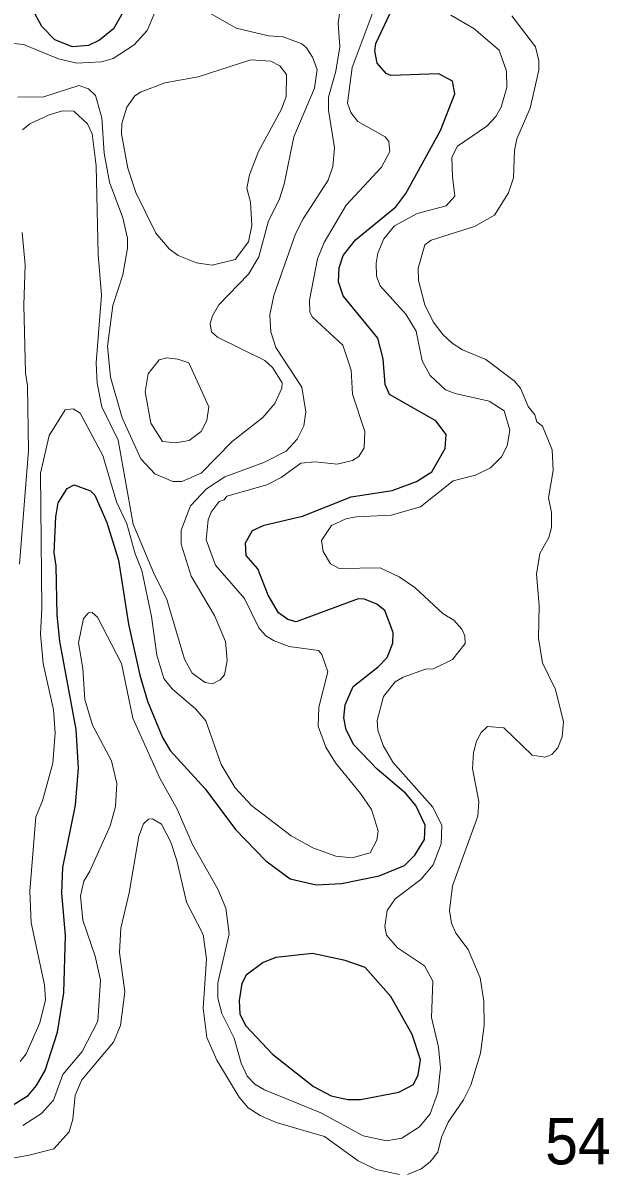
# Model space of a CAD drawing. Extents: x 673.6 to 698.9, y 7012 to 7040.1.
# Drawn here: x 681.449 to 682.459, y 7032.142 to 7034.12 of the extents above; entities that cross this region are included whole.
import ezdxf

# ---------------------------------------------------------------- set-up
doc = ezdxf.new("R2010")
doc.units = 0
doc.header["$LTSCALE"] = 0.032
doc.layers.add('1', color=7, linetype='Continuous', lineweight=25)
doc.layers.add('2', color=7, linetype='Continuous', lineweight=13)
doc.layers.add('21', color=7, linetype='Continuous')

msp = doc.modelspace()

# ---------------------------------------------------------------- linework, layer by layer
at = {"layer": '1'}
for points in [[(681.6055, 7034.1099), (681.5815, 7034.0904), (681.5621, 7034.0813), (681.5348, 7034.0789), (681.5041, 7034.0912), (681.4821, 7034.1139), (681.4666, 7034.1429), (681.4563, 7034.1779), (681.4556, 7034.1951), (681.4592, 7034.2083), (681.4778, 7034.2292), (681.4971, 7034.2413), (681.5311, 7034.2489), (681.5677, 7034.2464), (681.6015, 7034.231), (681.6232, 7034.214), (681.6297, 7034.1857), (681.6297, 7034.1606), (681.6192, 7034.1342)], [(682.0044, 7032.5048), (681.9485, 7032.5167), (681.8849, 7032.5102), (681.8631, 7032.5011), (681.8341, 7032.4793), (681.8267, 7032.4654), (681.8221, 7032.4357), (681.8228, 7032.4124), (681.8333, 7032.3919), (681.8796, 7032.3434), (681.95, 7032.2878), (681.9805, 7032.2715), (682.009, 7032.2653), (682.0308, 7032.2653), (682.0969, 7032.2777), (682.122, 7032.2909), (682.1301, 7032.3075), (682.1342, 7032.3334), (682.1197, 7032.3774), (682.0831, 7032.4428), (682.039, 7032.4928)]]:
    msp.add_lwpolyline(points, close=True, dxfattribs=at)
for points in [[(681.5066, 7033.1847), (681.5033, 7033.2074), (681.5062, 7033.2691), (681.5102, 7033.2932), (681.5255, 7033.318), (681.5376, 7033.3244), (681.5656, 7033.3138), (681.573, 7033.3064), (681.594, 7033.2596), (681.6142, 7033.1943), (681.6315, 7033.0842), (681.6505, 7032.9965), (681.6641, 7032.9514), (681.6898, 7032.8889), (681.7032, 7032.8667), (681.7631, 7032.8007), (681.8154, 7032.7303), (681.868, 7032.6763), (681.91, 7032.6455), (681.9548, 7032.6351), (681.9983, 7032.6376), (682.0628, 7032.6504), (682.1069, 7032.6686), (682.1244, 7032.6861), (682.1409, 7032.7132), (682.1425, 7032.7382), (682.1263, 7032.772), (682.1085, 7032.7931), (682.0595, 7032.8347), (682.0195, 7032.8763), (682.0062, 7032.9022), (682.0021, 7032.9227), (682.0046, 7032.9452), (682.0185, 7032.9769), (682.0614, 7033.0108), (682.0768, 7033.0266), (682.0867, 7033.0516), (682.0873, 7033.0701), (682.0728, 7033.1079), (682.059, 7033.1188), (682.0377, 7033.1271), (682.027, 7033.128), (681.9203, 7033.088), (681.9059, 7033.092), (681.8896, 7033.1035), (681.8717, 7033.1341), (681.8542, 7033.1795), (681.8338, 7033.2027), (681.8328, 7033.2242), (681.8451, 7033.2455), (681.8649, 7033.2546), (681.9309, 7033.2704), (682.0148, 7033.3039), (682.0854, 7033.3147), (682.1274, 7033.3301), (682.1537, 7033.3466), (682.1767, 7033.3872), (682.1784, 7033.4111), (682.1605, 7033.4346), (682.081, 7033.4799), (682.0736, 7033.4971), (682.0702, 7033.5414), (682.0606, 7033.5768), (682.001, 7033.6499), (681.993, 7033.6742), (681.9939, 7033.6983), (682.0009, 7033.7197), (682.0221, 7033.7463), (682.0919, 7033.8032), (682.109, 7033.8265), (682.169, 7033.9346), (682.1933, 7033.998), (682.1892, 7034.0196), (682.1659, 7034.0326), (682.0829, 7034.0295), (682.0751, 7034.0329), (682.0598, 7034.0506), (682.0555, 7034.072), (682.0572, 7034.0847), (682.0915, 7034.1577)], [(681.5401, 7032.7723), (681.545, 7032.8363), (681.541, 7032.9025), (681.513, 7033.0549), (681.5081, 7033.0997), (681.5066, 7033.1847)], [(681.4299, 7032.2541), (681.4585, 7032.2724), (681.4726, 7032.2895), (681.4876, 7032.3154), (681.509, 7032.3815), (681.5197, 7032.4489), (681.523, 7032.5477), (681.5164, 7032.6207), (681.518, 7032.665), (681.5401, 7032.7723)]]:
    msp.add_lwpolyline(points, dxfattribs=at)
at = {"layer": '2'}
for points in [[(681.997, 7034.1512), (681.9922, 7034.1199), (681.9954, 7034.0788), (681.9883, 7034.0373), (681.9758, 7033.9921), (681.9758, 7033.9697), (681.9863, 7033.905), (681.9834, 7033.873), (681.9751, 7033.8492), (681.932, 7033.7827), (681.9192, 7033.7567), (681.8815, 7033.6506), (681.8745, 7033.6174), (681.8762, 7033.5878), (681.8853, 7033.5611), (681.93, 7033.4926), (681.937, 7033.4502), (681.9335, 7033.4257), (681.9219, 7033.4028), (681.9027, 7033.3824), (681.8643, 7033.3628), (681.7971, 7033.3383), (681.7659, 7033.3177), (681.7381, 7033.288), (681.7218, 7033.246), (681.7219, 7033.2223), (681.739, 7033.1667), (681.7793, 7033.0993), (681.7983, 7033.0546), (681.8014, 7033.0214), (681.7968, 7032.9967), (681.7891, 7032.9882), (681.7758, 7032.9812), (681.7633, 7032.984), (681.7411, 7032.9996), (681.7276, 7033.0238), (681.6974, 7033.1267), (681.6741, 7033.1734), (681.6395, 7033.2563), (681.6134, 7033.4014), (681.5852, 7033.4588), (681.5773, 7033.4996), (681.5756, 7033.5345), (681.5846, 7033.6509), (681.5788, 7033.721), (681.5755, 7033.8738), (681.5689, 7033.9293), (681.5606, 7033.9465), (681.537, 7033.968), (681.5173, 7033.9686), (681.4947, 7033.962), (681.4615, 7033.9461), (681.4486, 7033.9362)], [(681.6765, 7034.138), (681.6636, 7034.1071), (681.641, 7034.0822), (681.6049, 7034.0586), (681.585, 7034.0534), (681.5423, 7034.051), (681.5106, 7034.0581), (681.4503, 7034.083), (681.4165, 7034.0862)], [(681.4407, 7033.9925), (681.4854, 7033.9926), (681.5459, 7034.0122), (681.5622, 7034.0067), (681.5745, 7033.9949), (681.5854, 7033.9569), (681.5895, 7033.8957), (681.5985, 7033.8459), (681.6216, 7033.7844), (681.6297, 7033.7492), (681.6297, 7033.7322), (681.6215, 7033.6861), (681.6042, 7033.6335), (681.5953, 7033.5633), (681.6002, 7033.5099), (681.6205, 7033.4397), (681.6526, 7033.3692), (681.6766, 7033.3434), (681.7074, 7033.3302), (681.7231, 7033.3302), (681.7565, 7033.3444), (681.8101, 7033.3988), (681.8628, 7033.4401), (681.8832, 7033.4644), (681.8956, 7033.4911), (681.896, 7033.5), (681.8795, 7033.5266), (681.8663, 7033.5388), (681.7845, 7033.5786), (681.7743, 7033.5881), (681.772, 7033.602), (681.776, 7033.6154), (681.7871, 7033.6345), (681.8381, 7033.6874), (681.8556, 7033.717), (681.8727, 7033.7791), (681.8909, 7033.8156), (681.8997, 7033.8423), (681.9163, 7033.9238), (681.9518, 7034.0079), (681.956, 7034.0398), (681.9483, 7034.0614), (681.9379, 7034.0772), (681.9297, 7034.0839), (681.8976, 7034.0961), (681.8723, 7034.0979), (681.8168, 7034.1111), (681.7738, 7034.1359)], [(681.5007, 7032.8446), (681.5048, 7032.8972), (681.5023, 7032.9366), (681.4842, 7033.0163), (681.4794, 7033.0673), (681.4819, 7033.1119), (681.4794, 7033.3446), (681.4948, 7033.4092), (681.5223, 7033.4534), (681.536, 7033.455), (681.5478, 7033.4477), (681.5873, 7033.3747), (681.6105, 7033.2952), (681.6281, 7033.2571), (681.6427, 7033.2053), (681.6544, 7033.1766), (681.6709, 7033.0974), (681.6798, 7033.0307), (681.6923, 7032.9909), (681.7062, 7032.9726), (681.7475, 7032.938), (681.7645, 7032.9177), (681.791, 7032.8426), (681.815, 7032.8025), (681.8429, 7032.7721), (681.9115, 7032.7193), (681.949, 7032.6989), (681.9884, 7032.6847), (682.0164, 7032.6819), (682.0478, 7032.6901), (682.0592, 7032.7123), (682.0612, 7032.7284), (682.0499, 7032.765), (682.031, 7032.7927), (681.9876, 7032.8453), (681.971, 7032.8722), (681.9581, 7032.9083), (681.9592, 7032.941), (681.9748, 7033.0023), (681.9642, 7033.0319), (681.9586, 7033.039), (681.9083, 7033.0457), (681.882, 7033.0554), (681.8678, 7033.0641), (681.8559, 7033.0779), (681.8308, 7033.1286), (681.7812, 7033.1861), (681.7653, 7033.2293), (681.7684, 7033.264), (681.7738, 7033.2772), (681.7874, 7033.2955), (681.7959, 7033.2985), (681.8009, 7033.3047), (681.8694, 7033.3244), (681.894, 7033.3367), (681.9284, 7033.3614), (681.9527, 7033.3639), (681.9909, 7033.3599), (682.0169, 7033.3661), (682.0278, 7033.3732), (682.0373, 7033.388), (682.0382, 7033.4162), (682.0172, 7033.4803), (682.0151, 7033.5217), (682.0003, 7033.5652), (681.9485, 7033.6134), (681.9437, 7033.622), (681.9432, 7033.6424), (681.9568, 7033.7137), (681.9681, 7033.7416), (682.0064, 7033.8063), (682.0669, 7033.8718), (682.0816, 7033.8984), (682.0795, 7033.916), (682.0732, 7033.9239), (682.0264, 7033.9503), (682.0142, 7033.9658), (682.0085, 7033.9822), (682.0165, 7034.0436), (682.0529, 7034.1397)], [(682.1864, 7034.1338), (682.2261, 7034.1103), (682.2699, 7034.0732), (682.2825, 7034.0368), (682.2829, 7034.0091), (682.273, 7033.975), (682.2643, 7033.9592), (682.2483, 7033.9423), (682.1981, 7033.9076), (682.188, 7033.8889), (682.1894, 7033.8553), (682.1934, 7033.8219), (682.1787, 7033.8049), (682.1283, 7033.792), (682.0897, 7033.7705), (682.0709, 7033.7482), (682.061, 7033.7232), (682.0579, 7033.7065), (682.0587, 7033.6838), (682.0647, 7033.6671), (682.1092, 7033.6184), (682.1269, 7033.5888), (682.1369, 7033.5378), (682.1508, 7033.5126), (682.1774, 7033.4879), (682.1938, 7033.4814), (682.2526, 7033.4682), (682.2785, 7033.452), (682.2879, 7033.4186), (682.2837, 7033.3916), (682.274, 7033.3724), (682.2549, 7033.3535), (682.229, 7033.3407), (682.1906, 7033.331), (682.134, 7033.2866), (682.084, 7033.272), (682.0235, 7033.2694), (682.0058, 7033.266), (681.9812, 7033.2544), (681.9635, 7033.2285), (681.9664, 7033.2096), (681.979, 7033.188), (681.9944, 7033.1799), (682.065, 7033.1815), (682.0978, 7033.166), (682.1247, 7033.1476), (682.1732, 7033.1022), (682.1918, 7033.0911), (682.2056, 7033.0758), (682.2108, 7033.0641), (682.2114, 7033.051), (682.1894, 7033.0235), (682.1564, 7033.0074), (682.1428, 7033.0065), (682.1044, 7032.9932), (682.0908, 7032.9851), (682.0704, 7032.9599), (682.0596, 7032.9181), (682.0609, 7032.9015), (682.0698, 7032.8753), (682.0865, 7032.8465), (682.1554, 7032.7692), (682.1712, 7032.7373), (682.1698, 7032.7056), (682.1561, 7032.6697), (682.1348, 7032.6446), (682.0909, 7032.6111), (682.0768, 7032.591), (682.0726, 7032.5632), (682.0759, 7032.5485), (682.0947, 7032.5268), (682.1412, 7032.4958), (682.1558, 7032.4693), (682.1533, 7032.4063), (682.1654, 7032.3555), (682.1688, 7032.3193), (682.1639, 7032.2776), (682.1512, 7032.2408), (682.1327, 7032.2184), (682.102, 7032.1986), (682.0757, 7032.1938), (682.0354, 7032.2029), (681.9625, 7032.2422), (681.8654, 7032.2821), (681.8487, 7032.2918), (681.8357, 7032.3057), (681.8254, 7032.3281), (681.813, 7032.3712), (681.7918, 7032.4137), (681.7849, 7032.4397), (681.7853, 7032.4665), (681.8047, 7032.5505), (681.7988, 7032.595), (681.7849, 7032.6279)], [(682.2082, 7032.2644), (682.2208, 7032.2898), (682.2378, 7032.345), (682.2438, 7032.3926), (682.2436, 7032.4344), (682.2372, 7032.4749), (682.2166, 7032.5238), (682.1953, 7032.5517), (682.1875, 7032.5692), (682.1844, 7032.5907), (682.1892, 7032.6336), (682.233, 7032.7532), (682.2345, 7032.7788), (682.2238, 7032.8356), (682.2256, 7032.863), (682.2309, 7032.8828), (682.2389, 7032.8975), (682.2497, 7032.9082), (682.2779, 7032.9054), (682.3268, 7032.8587), (682.3489, 7032.8553), (682.3603, 7032.8595), (682.3707, 7032.8711), (682.3786, 7032.89), (682.3808, 7032.9162), (682.3667, 7032.9714), (682.3445, 7033.0178), (682.3373, 7033.0604), (682.3389, 7033.1164), (682.334, 7033.1704), (682.3397, 7033.2058), (682.3552, 7033.2338), (682.3602, 7033.2506), (682.3602, 7033.2768), (682.3546, 7033.3018), (682.3627, 7033.3488), (682.3612, 7033.3846), (682.3444, 7033.4256), (682.3348, 7033.4326), (682.3314, 7033.4452), (682.32, 7033.4592), (682.3065, 7033.4906), (682.2957, 7033.5034), (682.2468, 7033.5402), (682.2067, 7033.557), (682.1888, 7033.5683), (682.1725, 7033.5835), (682.1561, 7033.6049), (682.142, 7033.6345), (682.1307, 7033.6761), (682.1303, 7033.6979), (682.1418, 7033.7378), (682.1525, 7033.746), (682.2273, 7033.7697), (682.2617, 7033.7891), (682.2857, 7033.8277), (682.2944, 7033.8531), (682.2962, 7033.9003), (682.3, 7033.9203), (682.3232, 7033.9734), (682.3382, 7034.039), (682.338, 7034.0549), (682.3322, 7034.0791), (682.2914, 7034.1323)], [(681.4481, 7033.7588), (681.453, 7033.7033), (681.4507, 7033.634), (681.454, 7033.5171), (681.4572, 7033.4951), (681.4588, 7033.3833), (681.4433, 7033.1877)], [(681.6193, 7033.0165), (681.5778, 7033.0962), (681.5686, 7033.1042), (681.5624, 7033.104), (681.5536, 7033.0938), (681.5452, 7033.052), (681.5523, 7033.008), (681.5558, 7032.9544), (681.5691, 7032.91), (681.6022, 7032.849), (681.6109, 7032.8099), (681.6091, 7032.77), (681.5995, 7032.7368), (681.5648, 7032.6589), (681.5542, 7032.6413), (681.5484, 7032.6161), (681.5527, 7032.5745), (681.5739, 7032.5123), (681.5828, 7032.4706), (681.5784, 7032.4002), (681.5514, 7032.348), (681.5182, 7032.3082), (681.5022, 7032.2643), (681.4815, 7032.2411), (681.4492, 7032.2206)], [(681.7849, 7032.6279), (681.7417, 7032.7046), (681.7152, 7032.7657), (681.6852, 7032.819), (681.6386, 7032.9225), (681.6193, 7033.0165)], [(681.4868, 7032.463), (681.4635, 7032.5699), (681.4612, 7032.6242), (681.4719, 7032.7522), (681.483, 7032.7801), (681.5007, 7032.8446)], [(681.3655, 7032.1519), (681.46, 7032.1691), (681.5029, 7032.1805), (681.5291, 7032.2096), (681.5355, 7032.2314), (681.5393, 7032.2726), (681.551, 7032.2992), (681.6054, 7032.3641), (681.6175, 7032.3929), (681.6249, 7032.4507), (681.6158, 7032.5185), (681.6179, 7032.5604), (681.6322, 7032.6211), (681.649, 7032.7191), (681.6571, 7032.7404), (681.6658, 7032.7482), (681.6725, 7032.7491), (681.6882, 7032.7399), (681.7044, 7032.7085), (681.7148, 7032.6769), (681.7314, 7032.6053), (681.7601, 7032.5494), (681.7654, 7032.5078), (681.7596, 7032.4227), (681.766, 7032.3722), (681.7836, 7032.3331), (681.8217, 7032.2695), (681.8372, 7032.2509), (681.8579, 7032.2375), (681.8856, 7032.2259), (681.9689, 7032.2016), (682.0269, 7032.1596), (682.0581, 7032.1448), (682.098, 7032.1359)], [(681.4447, 7032.331), (681.4547, 7032.3442), (681.4784, 7032.3972), (681.4884, 7032.4371), (681.4868, 7032.463)], [(682.1352, 7032.146), (682.1509, 7032.1577), (682.1639, 7032.1744), (682.1706, 7032.2006), (682.1817, 7032.2261), (682.2082, 7032.2644)], [(682.1118, 7032.1363), (682.1352, 7032.146)]]:
    msp.add_lwpolyline(points, dxfattribs=at)
for points in [[(681.8418, 7034.0566), (681.8763, 7034.0542), (681.8921, 7034.0464), (681.9033, 7034.0314), (681.9029, 7033.9935), (681.8948, 7033.9715), (681.855, 7033.8985), (681.8396, 7033.8582), (681.8353, 7033.8357), (681.8416, 7033.8113), (681.8435, 7033.7711), (681.8382, 7033.743), (681.8152, 7033.7125), (681.7755, 7033.7026), (681.7485, 7033.7066), (681.717, 7033.7193), (681.7012, 7033.7312), (681.6784, 7033.7577), (681.6436, 7033.8279), (681.6299, 7033.8698), (681.6191, 7033.929), (681.62, 7033.9468), (681.6283, 7033.9753), (681.6424, 7033.9944), (681.6518, 7034.0011), (681.6938, 7034.0171), (681.7511, 7034.0271)], [(681.735, 7033.5343), (681.7162, 7033.5408), (681.6974, 7033.5431), (681.6841, 7033.5397), (681.6652, 7033.5154), (681.6602, 7033.4848), (681.6698, 7033.4304), (681.6898, 7033.3991), (681.713, 7033.3969), (681.736, 7033.4008), (681.7566, 7033.416), (681.7662, 7033.4349), (681.7694, 7033.4585)]]:
    msp.add_lwpolyline(points, close=True, dxfattribs=at)

# ---------------------------------------------------------------- texts
at = {"layer": '21', "width": 0.95}
msp.add_text('54', height=0.08, dxfattribs=at).set_placement((682.349, 7032.1535))

doc.saveas('drawing.dxf')
